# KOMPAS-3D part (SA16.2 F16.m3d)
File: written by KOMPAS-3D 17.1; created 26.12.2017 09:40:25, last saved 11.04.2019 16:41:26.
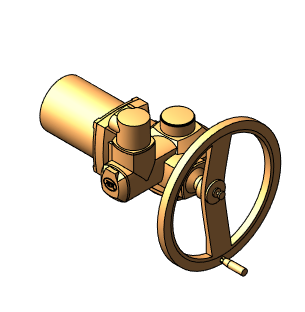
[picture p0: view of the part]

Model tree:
1. Операция без истории:6  (labels: Сталь 20  ГОСТ 1050-2013)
